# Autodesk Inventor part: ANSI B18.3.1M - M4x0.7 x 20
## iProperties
Comments: To add or edit properties for Autodesk Inventor files, use iProperties.
Created: 2004-08
Part Number: ANSI B18.3.1M - M4x0.7 x 20
Vendor: Autodesk Inc.
Document SubType Name: Modeling
Designer: John Blackburn
Material: Default
Description: Forged Socket Head Cap Screw x Metric
Standard: ANSI B18.3.1M
Alert: To add or edit properties for Autodesk Inventor files, use iProperties.
Control State: 0
Master: False
Checked Out: False
Shininess: 64.0
Length Units: 11269
Angle Units: 11279
Time Units: 11290
Mass Units: 11283
Length Display Precision: 3
Angle Display Precision: 2
Compacted: True
EGR: 1
Classification: un/spsc 31161501
Density: 0.0
Volumn: 0.0
Area: 0.0
PropertySet Name: Model Information
Author: John Blackburn
Revision Number: 8
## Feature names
1. Body [Revolution]
2. Slot [Extrusion]
3. Fillet1
4. Chamfer1
